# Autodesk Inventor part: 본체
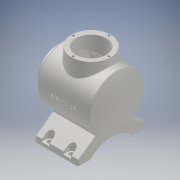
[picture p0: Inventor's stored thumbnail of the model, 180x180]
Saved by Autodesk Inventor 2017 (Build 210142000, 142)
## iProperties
Part Number: 본체
Material: 알루미늄 6061
Document SubType Name: Modeling
Designer: MRC
Density: 2.7 g/cm^3
Appearance: 알루미늄 - 평지
Mass: 1296.69 g
Surface Area: 1060.44 cm^2
Volume: 480.256 cm^3
Author: MRC
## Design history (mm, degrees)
sketch "스케치2"
  geometry: L1 (0, 0)-(0, 36); L2 (0, 36)-(12, 36); L3 (12, 36)-(12, 50); L4 (12, 50)-(108.336, 50); L5 (120, 0)-(0, 0); A1 r 113 centre (7, 0) between (120, 0) and (108.336, 50)
  constraints: 10 end point, 3 perpendicular, 2 point on circle, 1 centre point, 1 horizontal, 1 point on line, 1 vertical
  dimensions: "d0" = 113 radius of A1; "d1" = 72 diameter of L2 L5; "d2" = 100 diameter of L4 L5; "d3" = 120 distance of L5.start L1.start; "d4" = 108 distance from line of L5.start L3
revolve "회전1" sketch "스케치2" stored, may be unused: angle "d5" = 90 deg
node "작업 평면1"
sketch "스케치3"
  geometry: C1 r 36 at (62, 0); 1 further point
  constraints: 1 centre point, 1 horizontal alignment
  dimensions: "d7" = 72 diameter of C1; "d8" = 62 distance of point (0, 0) C1.centre
extrude "돌출1" join sketch "스케치3" stored distance "d9" = 10; taper "d10" = 0 deg
sketch "스케치4"
  geometry: L1 (0, 0)-(0, 27); L2 (0, 27)-(-19, 27); L3 (-19, 27)-(-19, 43); L4 (-19, 43)-(-103.887, 43); L5 (0, 0)-(-113, 0); A1 r 106 centre (-7, 0) between (-103.887, 43) and (-113, 0)
  constraints: 10 end point, 3 perpendicular, 2 point on circle, 1 centre point, 1 horizontal, 1 point on line, 1 vertical
  dimensions: "d12" = 19 distance of L1.end L2.end; "d13" = 54 diameter of L2 L5; "d14" = 86 diameter of L4 L5; "d15" = 106 radius of A1; "d16" = 113 distance of L1.start L5.end
revolve "회전2" sketch "스케치4" stored, may be unused: angle "d17" = 90 deg
sketch "스케치5"
  geometry: C1 r 36 at (0, 0) reference; C2 r 27 at (0, 0); 1 further point
  constraints: 1 centre point, 1 coincident
  dimensions: "d18" = 54 diameter of C2
extrude "돌출2" cut sketch "스케치5" stored distance "d19" = 10; taper "d20" = 0 deg
node "작업 평면2"
sketch "스케치6"
  geometry: L1 (26.694, -42.278)-(62, -67); L2 (62, -67)-(62, -77); L3 (62, -77)-(38.5, -77); L4 (-38.5, -77)-(-62, -77); L5 (-62, -77)-(-62, -67); L6 (-62, -67)-(-26.694, -42.278); L7 (0, 0)-(-50, 0); L8 (0, 0)-(0, 50); L9 (0, -112.096)-(0, -60); A1 r 52.096 centre (0, -112.096) between (38.5, -77) and (-38.5, -77); A2 r 50 centre (0, 0) between (26.694, -42.278) and (-26.694, -42.278) reference
  constraints: 18 end point, 7 point on circle, 3 vertical, 2 horizontal, 2 perpendicular, 1 centre point, 1 collinear, 1 symmetric about line, 1 vertical alignment, 1 other
  dimensions: "d22" = 10 distance of L1.end L2.end; "d23" = 10 distance of L4.end L5.end; "d24" = 77 distance of L4.start L3.end; "d25" = 17 distance from line of L4 L9.end; "d26" = 55 deg angle of L5 L6; "d27" = 77 distance between parallel lines of L7 L4; "d28" = 124 distance between parallel lines of L5 L2
extrude "돌출3" join sketch "스케치6" distance "d29" = 80; taper "d30" = 0 deg
sketch "스케치7"
  geometry: L1 (0, 0)-(-80, 0) reference; L2 (0, 0)-(0, 23.5) reference; 5 further points
  constraints: 2 horizontal alignment, 2 vertical alignment
  dimensions: "d31" = 108 distance of point (-20, 8) point (-20, 116); "d32" = 8 distance from line of L1 point (-20, 8); "d33" = 40 distance of point (-60, 8) point (-20, 8); "d34" = 20 distance from line of L2 point (-20, 8)
hole "구멍1" sketch "스케치7" at (-20, 116), (-20, 8), (-60, 116), (-60, 8) diameter "d35" = 9; stored, may be unused: countersink angle "d39" = 90 deg, drill point angle "d41" = 0 deg; dims "d36" = 6, "d37" = 4, "d38" = 2, "d40" = 6
sketch "스케치8"
  geometry: L1 (7, -8)-(7, 0); L2 (20, -8)-(-60, -8) reference; L3 (-7, 0)-(-7, -8); C1 r 4.5 at (0, 0) reference; A1 r 7 centre (0, 0) between (7, 0) and (-7, 0); 1 further point
  constraints: 4 end point, 4 point on circle, 4 point on line, 2 tangent, 2 vertical, 1 centre point, 1 coincident
  dimensions: "d42" = 14 diameter of A1
extrude "돌출4" cut sketch "스케치8" stored distance "d43" = 80; taper "d44" = 0 deg
node "작업 평면3"
sketch "스케치9"
  geometry: L1 (0, 0)-(0, 27); 2 further points
  constraints: 2 end point, 1 horizontal alignment, 1 vertical, 1 vertical alignment, 1 other
  dimensions: "d47" = 32.5 distance from line of L1 point (-32.5, 0)
hole "구멍2" sketch "스케치9" at (-32.5, 0) diameter "d48" = 3.242; stored, may be unused: countersink angle "d52" = 90 deg, drill point angle "d54" = 118 deg; dims "d49" = 8, "d50" = 4, "d51" = 2, "d53" = 10
sketch "스케치10"
  geometry: 2 further points
  constraints: 1 horizontal alignment
  dimensions: "d58" = 32.5 distance of point (0, 0) point (32.5, 0)
hole "구멍3" sketch "스케치10" at (32.5, 0) diameter "d59" = 3.242; stored, may be unused: countersink angle "d63" = 90 deg, drill point angle "d65" = 118 deg; dims "d60" = 8, "d61" = 4, "d62" = 2, "d64" = 10
chamfer "모따기1" distance "d69" = 1; stored, may be unused: second distance "d70" = 2, angle "d71" = 45 deg
fillet "모깎기1" dims "d72" = 3
fillet "모깎기2" dims "d73" = 3
fillet "모깎기3" dims "d74" = 3
fillet "모깎기4" dims "d75" = 3
fillet "모깎기5" dims "d76" = 3
node "작업 평면4"
sketch "스케치11"
  geometry: L1 (0, -36)-(0, 36) reference; 3 further points
  constraints: 1 horizontal alignment, 1 midpoint, 1 other
  dimensions: "d78" = 62 distance from line of L1 point (62, 0)
feature "엠보싱1" sketch "스케치11" dims "d0" = 113, "d1" = 72, "d2" = 100, "d3" = 120, "d4" = 108, "d15" = 106, "d79" = 0.5, "d80" = 0
node "솔리드1"
mirror "미러1"
mirror "미러2"
pattern_circular "원형 패턴1" dims angle "d56" = 360 deg
pattern_circular "원형 패턴2" dims angle "d67" = 360 deg
other parameters: "d6" = 65, "d77" = -94.25
